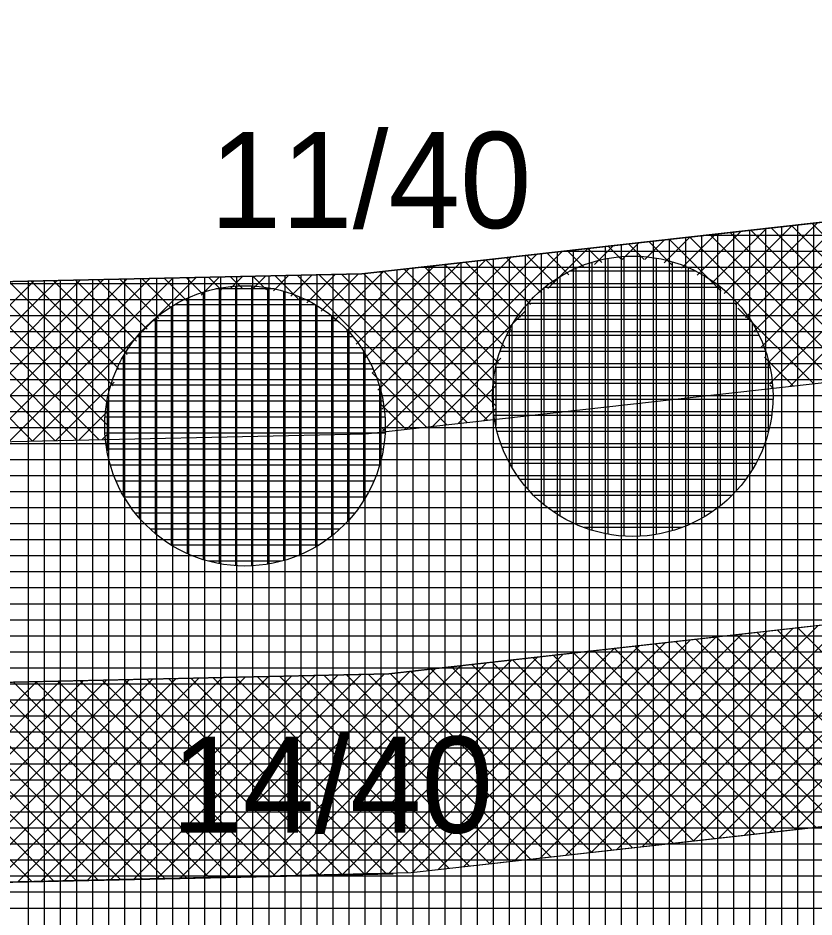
# Model space of a CAD drawing. Extents: x -566461 to -565198, y -1096301 to -1095707.
# Drawn here: x -565614.79 to -565604.86, y -1095879.32 to -1095868.1 of the extents above; entities that cross this region are included whole.
import ezdxf

# ---------------------------------------------------------------- set-up
doc = ezdxf.new("R2010")
doc.units = 0
for name, color, linetype in [('Vrstva 13', 7, 'Continuous'), ('Vrstva 40', 7, 'Continuous'), ('Vrstva 41', 7, 'Continuous'), ('Vrstva 42', 7, 'Continuous'), ('Vrstva 43', 7, 'Continuous'), ('Vrstva 44', 7, 'Continuous')]:
    doc.layers.add(name, color=color, linetype=linetype)

msp = doc.modelspace()

# ---------------------------------------------------------------- linework, layer by layer
at = {"layer": 'Vrstva 13'}
for p, q in [((-565610.5, -1095871.29), (-565587.97, -1095868.76)), ((-565630.22, -1095871.73), (-565610.5, -1095871.29)), ((-565610.165, -1095876.284), (-565587.281, -1095873.714)), ((-565609.886, -1095878.768), (-565587.002, -1095876.198)), ((-565630.41, -1095876.736), (-565610.165, -1095876.284)), ((-565630.354, -1095879.235), (-565610.109, -1095878.783))]:
    msp.add_line(p, q, dxfattribs=at)
at = {"layer": 'Vrstva 41'}
for p, q in [((-565605.453, -1095872.423), (-565603.537, -1095870.508)), ((-565605.413, -1095872.666), (-565603.219, -1095870.472)), ((-565605.161, -1095872.697), (-565602.9, -1095870.437)), ((-565605.715, -1095871.838), (-565604.493, -1095870.615)), ((-565605.608, -1095872.013), (-565604.175, -1095870.58)), ((-565605.52, -1095872.208), (-565603.856, -1095870.544)), ((-565606.14, -1095871.414), (-565605.449, -1095870.723)), ((-565605.981, -1095871.538), (-565605.131, -1095870.687)), ((-565605.839, -1095871.679), (-565604.812, -1095870.651)), ((-565603.809, -1095872.302), (-565605.395, -1095870.717)), ((-565603.807, -1095872.022), (-565605.141, -1095870.688)), ((-565603.767, -1095871.779), (-565604.886, -1095870.66)), ((-565606.727, -1095871.152), (-565606.405, -1095870.83)), ((-565606.511, -1095871.219), (-565606.086, -1095870.794)), ((-565604.608, -1095872.635), (-565606.412, -1095870.831)), ((-565606.316, -1095871.307), (-565605.768, -1095870.759)), ((-565604.353, -1095872.607), (-565606.158, -1095870.802)), ((-565604.099, -1095872.578), (-565605.903, -1095870.774)), ((-565603.844, -1095872.55), (-565605.649, -1095870.745)), ((-565607.597, -1095871.174), (-565607.361, -1095870.937)), ((-565607.262, -1095871.112), (-565607.429, -1095870.945)), ((-565607.252, -1095871.112), (-565607.042, -1095870.902)), ((-565606.979, -1095871.112), (-565607.175, -1095870.917)), ((-565606.97, -1095871.113), (-565606.724, -1095870.866)), ((-565606.632, -1095871.177), (-565606.921, -1095870.888)), ((-565606.018, -1095871.508), (-565606.666, -1095870.859)), ((-565610.253, -1095872.981), (-565608.317, -1095871.045)), ((-565610.245, -1095873.256), (-565607.998, -1095871.009)), ((-565608.095, -1095871.411), (-565608.446, -1095871.059)), ((-565607.919, -1095871.304), (-565608.192, -1095871.031)), ((-565608.181, -1095871.475), (-565607.68, -1095870.973)), ((-565607.724, -1095871.216), (-565607.938, -1095871.002)), ((-565607.507, -1095871.15), (-565607.683, -1095870.974)), ((-565610.462, -1095872.342), (-565609.273, -1095871.152)), ((-565610.371, -1095872.533), (-565608.954, -1095871.116)), ((-565610.3, -1095872.745), (-565608.635, -1095871.081)), ((-565608.629, -1095872.008), (-565609.464, -1095871.174)), ((-565608.522, -1095871.833), (-565609.209, -1095871.145)), ((-565608.397, -1095871.674), (-565608.955, -1095871.116)), ((-565608.254, -1095871.534), (-565608.701, -1095871.088)), ((-565611.009, -1095871.757), (-565610.543, -1095871.291)), ((-565610.848, -1095871.879), (-565610.229, -1095871.26)), ((-565608.932, -1095873.119), (-565610.756, -1095871.296)), ((-565610.703, -1095872.016), (-565609.91, -1095871.224)), ((-565610.573, -1095872.17), (-565609.591, -1095871.188)), ((-565608.829, -1095872.939), (-565610.481, -1095871.288)), ((-565608.827, -1095872.659), (-565610.226, -1095871.259)), ((-565608.786, -1095872.417), (-565609.972, -1095871.231)), ((-565608.718, -1095872.202), (-565609.718, -1095871.202)), ((-565613.781, -1095873.362), (-565615.736, -1095871.407)), ((-565613.681, -1095873.178), (-565615.459, -1095871.401)), ((-565615.422, -1095872.21), (-565614.593, -1095871.381)), ((-565615.303, -1095872.374), (-565614.304, -1095871.375)), ((-565615.201, -1095872.556), (-565614.014, -1095871.368)), ((-565613.658, -1095872.919), (-565615.182, -1095871.394)), ((-565615.119, -1095872.756), (-565613.725, -1095871.362)), ((-565615.062, -1095872.981), (-565613.436, -1095871.356)), ((-565615.033, -1095873.236), (-565613.146, -1095871.349)), ((-565613.605, -1095872.689), (-565614.906, -1095871.388)), ((-565614.901, -1095873.386), (-565612.857, -1095871.343)), ((-565613.529, -1095872.482), (-565614.629, -1095871.382)), ((-565614.611, -1095873.38), (-565612.568, -1095871.336)), ((-565613.431, -1095872.298), (-565614.352, -1095871.376)), ((-565613.315, -1095872.131), (-565614.076, -1095871.37)), ((-565613.182, -1095871.981), (-565613.799, -1095871.364)), ((-565613.033, -1095871.847), (-565613.522, -1095871.357)), ((-565612.868, -1095871.729), (-565613.246, -1095871.351)), ((-565612.685, -1095871.63), (-565612.969, -1095871.345)), ((-565612.481, -1095871.55), (-565612.692, -1095871.339)), ((-565612.508, -1095871.559), (-565612.279, -1095871.33)), ((-565612.253, -1095871.496), (-565612.416, -1095871.333)), ((-565612.145, -1095871.479), (-565611.989, -1095871.323)), ((-565611.996, -1095871.47), (-565612.139, -1095871.327)), ((-565611.691, -1095871.492), (-565611.862, -1095871.32)), ((-565611.857, -1095871.474), (-565611.7, -1095871.317)), ((-565611.606, -1095871.505), (-565611.411, -1095871.31)), ((-565611.297, -1095871.603), (-565611.586, -1095871.314)), ((-565611.386, -1095871.569), (-565611.121, -1095871.304)), ((-565609.441, -1095873.176), (-565611.309, -1095871.308)), ((-565611.188, -1095871.654), (-565610.832, -1095871.297)), ((-565609.186, -1095873.148), (-565611.032, -1095871.302)), ((-565614.058, -1095873.368), (-565616.012, -1095871.413)), ((-565604.862, -1095872.664), (-565605.808, -1095871.718)), ((-565609.938, -1095873.232), (-565608.465, -1095871.759)), ((-565609.62, -1095873.197), (-565608.766, -1095872.343)), ((-565605.116, -1095872.692), (-565605.477, -1095872.332)), ((-565614.334, -1095873.374), (-565615.252, -1095872.457)), ((-565609.695, -1095873.205), (-565610.373, -1095872.527)), ((-565614.322, -1095873.374), (-565613.591, -1095872.642)), ((-565609.301, -1095873.161), (-565608.828, -1095872.688)), ((-565605.371, -1095872.721), (-565605.412, -1095872.679)), ((-565614.611, -1095873.38), (-565615.075, -1095872.916)), ((-565609.949, -1095873.233), (-565610.262, -1095872.921)), ((-565608.983, -1095873.125), (-565608.827, -1095872.97)), ((-565614.033, -1095873.367), (-565613.671, -1095873.005)), ((-565613.744, -1095873.361), (-565613.676, -1095873.293)), ((-565610.204, -1095873.262), (-565610.242, -1095873.224)), ((-565605.408, -1095878.265), (-565602.575, -1095875.432)), ((-565605.09, -1095878.229), (-565602.256, -1095875.396)), ((-565606.364, -1095878.372), (-565603.531, -1095875.539)), ((-565606.046, -1095878.337), (-565603.212, -1095875.503)), ((-565605.727, -1095878.301), (-565602.893, -1095875.467)), ((-565607.32, -1095878.48), (-565604.486, -1095875.646)), ((-565607.001, -1095878.444), (-565604.168, -1095875.61)), ((-565606.683, -1095878.408), (-565603.849, -1095875.575)), ((-565608.276, -1095878.587), (-565605.442, -1095875.754)), ((-565607.957, -1095878.551), (-565605.124, -1095875.718)), ((-565607.639, -1095878.516), (-565604.805, -1095875.682)), ((-565603.309, -1095878.029), (-565605.57, -1095875.768)), ((-565603.055, -1095878.001), (-565605.316, -1095875.739)), ((-565602.801, -1095877.972), (-565605.062, -1095875.711)), ((-565609.55, -1095878.73), (-565606.717, -1095875.897)), ((-565609.232, -1095878.695), (-565606.398, -1095875.861)), ((-565608.913, -1095878.659), (-565606.08, -1095875.825)), ((-565608.595, -1095878.623), (-565605.761, -1095875.789)), ((-565604.326, -1095878.144), (-565606.588, -1095875.882)), ((-565604.072, -1095878.115), (-565606.333, -1095875.854)), ((-565603.818, -1095878.086), (-565606.079, -1095875.825)), ((-565603.563, -1095878.058), (-565605.825, -1095875.797)), ((-565610.449, -1095878.781), (-565607.673, -1095876.004)), ((-565610.16, -1095878.774), (-565607.354, -1095875.968)), ((-565609.869, -1095878.766), (-565607.035, -1095875.933)), ((-565605.343, -1095878.258), (-565607.605, -1095875.996)), ((-565605.089, -1095878.229), (-565607.35, -1095875.968)), ((-565604.835, -1095878.201), (-565607.096, -1095875.939)), ((-565604.581, -1095878.172), (-565606.842, -1095875.911)), ((-565611.318, -1095878.801), (-565608.629, -1095876.111)), ((-565611.028, -1095878.794), (-565608.31, -1095876.076)), ((-565610.739, -1095878.787), (-565607.991, -1095876.04)), ((-565606.361, -1095878.372), (-565608.622, -1095876.111)), ((-565606.106, -1095878.344), (-565608.368, -1095876.082)), ((-565605.852, -1095878.315), (-565608.113, -1095876.054)), ((-565605.598, -1095878.286), (-565607.859, -1095876.025)), ((-565612.186, -1095878.82), (-565609.584, -1095876.219)), ((-565611.897, -1095878.814), (-565609.266, -1095876.183)), ((-565611.607, -1095878.807), (-565608.947, -1095876.147)), ((-565607.378, -1095878.486), (-565609.639, -1095876.225)), ((-565607.123, -1095878.458), (-565609.385, -1095876.196)), ((-565606.869, -1095878.429), (-565609.13, -1095876.168)), ((-565606.615, -1095878.401), (-565608.876, -1095876.139)), ((-565615.37, -1095878.893), (-565612.82, -1095876.343)), ((-565615.081, -1095878.887), (-565612.531, -1095876.337)), ((-565614.791, -1095878.88), (-565612.242, -1095876.33)), ((-565614.502, -1095878.873), (-565611.952, -1095876.324)), ((-565614.212, -1095878.867), (-565611.663, -1095876.317)), ((-565613.923, -1095878.86), (-565611.374, -1095876.311)), ((-565613.633, -1095878.854), (-565611.084, -1095876.305)), ((-565613.344, -1095878.847), (-565610.795, -1095876.298)), ((-565613.055, -1095878.84), (-565610.506, -1095876.292)), ((-565610.477, -1095878.781), (-565612.913, -1095876.345)), ((-565612.765, -1095878.834), (-565610.217, -1095876.285)), ((-565610.2, -1095878.775), (-565612.636, -1095876.339)), ((-565612.476, -1095878.827), (-565609.903, -1095876.255)), ((-565609.924, -1095878.769), (-565612.359, -1095876.333)), ((-565609.666, -1095878.743), (-565612.083, -1095876.327)), ((-565609.412, -1095878.715), (-565611.806, -1095876.321)), ((-565609.158, -1095878.686), (-565611.529, -1095876.314)), ((-565608.903, -1095878.658), (-565611.253, -1095876.308)), ((-565608.649, -1095878.629), (-565610.976, -1095876.302)), ((-565608.395, -1095878.601), (-565610.699, -1095876.296)), ((-565608.141, -1095878.572), (-565610.423, -1095876.29)), ((-565607.886, -1095878.543), (-565610.148, -1095876.282)), ((-565607.632, -1095878.515), (-565609.893, -1095876.253)), ((-565617.107, -1095878.933), (-565614.556, -1095876.382)), ((-565614.625, -1095878.876), (-565617.063, -1095876.438)), ((-565616.817, -1095878.926), (-565614.267, -1095876.376)), ((-565614.348, -1095878.87), (-565616.786, -1095876.432)), ((-565616.528, -1095878.92), (-565613.977, -1095876.369)), ((-565614.072, -1095878.863), (-565616.509, -1095876.426)), ((-565616.238, -1095878.913), (-565613.688, -1095876.363)), ((-565613.795, -1095878.857), (-565616.233, -1095876.419)), ((-565613.518, -1095878.851), (-565615.956, -1095876.413)), ((-565615.949, -1095878.906), (-565613.399, -1095876.356)), ((-565613.242, -1095878.845), (-565615.679, -1095876.407)), ((-565615.66, -1095878.9), (-565613.11, -1095876.35)), ((-565612.965, -1095878.838), (-565615.403, -1095876.401)), ((-565612.689, -1095878.832), (-565615.126, -1095876.395)), ((-565612.412, -1095878.826), (-565614.849, -1095876.389)), ((-565612.136, -1095878.819), (-565614.573, -1095876.382)), ((-565611.859, -1095878.813), (-565614.296, -1095876.376)), ((-565611.583, -1095878.807), (-565614.019, -1095876.37)), ((-565611.306, -1095878.8), (-565613.743, -1095876.364)), ((-565611.03, -1095878.794), (-565613.466, -1095876.358)), ((-565610.753, -1095878.788), (-565613.189, -1095876.352))]:
    msp.add_line(p, q, dxfattribs=at)
at = {"layer": 'Vrstva 42'}
for points in [[(-565642.21, -1095870.56), (-565642.251, -1095872.566), (-565630.414, -1095873.721), (-565610.455, -1095873.29), (-565587.747, -1095870.748), (-565569.297, -1095867.734), (-565519.622, -1095865.105), (-565519.36, -1095863.08), (-565569.62, -1095865.76), (-565587.97, -1095868.76), (-565610.5, -1095871.29), (-565630.22, -1095871.73)], [(-565642.542, -1095875.552), (-565642.365, -1095878.081), (-565630.354, -1095879.235), (-565609.886, -1095878.768), (-565587.002, -1095876.198), (-565568.675, -1095873.205), (-565520.341, -1095870.651), (-565520.014, -1095868.13), (-565569.078, -1095870.738), (-565587.281, -1095873.714), (-565610.165, -1095876.284), (-565630.41, -1095876.736)]]:
    msp.add_lwpolyline(points, close=True, dxfattribs=at)
at = {"layer": 'Vrstva 43'}
for p, q in [((-565605.46, -1095885.817), (-565605.46, -1095870.724)), ((-565605.26, -1095885.794), (-565605.26, -1095870.702)), ((-565605.06, -1095885.772), (-565605.06, -1095870.679)), ((-565604.86, -1095885.75), (-565604.86, -1095870.657)), ((-565606.46, -1095885.929), (-565606.46, -1095870.836)), ((-565606.26, -1095885.907), (-565606.26, -1095870.814)), ((-565606.226, -1095870.81), (-565520.361, -1095870.81)), ((-565606.06, -1095885.884), (-565606.06, -1095870.791)), ((-565605.86, -1095885.862), (-565605.86, -1095870.769)), ((-565605.66, -1095885.839), (-565605.66, -1095870.746)), ((-565607.46, -1095886.042), (-565607.46, -1095870.949)), ((-565607.26, -1095886.019), (-565607.26, -1095870.926)), ((-565607.06, -1095885.997), (-565607.06, -1095870.904)), ((-565606.86, -1095885.974), (-565606.86, -1095870.881)), ((-565606.66, -1095885.952), (-565606.66, -1095870.859)), ((-565608.46, -1095886.154), (-565608.46, -1095871.061)), ((-565608.26, -1095886.132), (-565608.26, -1095871.038)), ((-565608.06, -1095886.109), (-565608.06, -1095871.016)), ((-565608.007, -1095871.01), (-565520.387, -1095871.01)), ((-565607.86, -1095886.087), (-565607.86, -1095870.994)), ((-565607.66, -1095886.064), (-565607.66, -1095870.971)), ((-565609.46, -1095886.267), (-565609.46, -1095871.173)), ((-565609.26, -1095886.244), (-565609.26, -1095871.151)), ((-565609.06, -1095886.222), (-565609.06, -1095871.128)), ((-565608.86, -1095886.199), (-565608.86, -1095871.106)), ((-565608.66, -1095886.177), (-565608.66, -1095871.083)), ((-565610.66, -1095886.296), (-565610.66, -1095871.294)), ((-565610.46, -1095886.292), (-565610.46, -1095871.286)), ((-565610.26, -1095886.287), (-565610.26, -1095871.263)), ((-565610.06, -1095886.283), (-565610.06, -1095871.241)), ((-565609.86, -1095886.278), (-565609.86, -1095871.218)), ((-565609.788, -1095871.21), (-565520.413, -1095871.21)), ((-565609.66, -1095886.274), (-565609.66, -1095871.196)), ((-565614.66, -1095886.387), (-565614.66, -1095871.383)), ((-565614.46, -1095886.382), (-565614.46, -1095871.378)), ((-565614.26, -1095886.378), (-565614.26, -1095871.374)), ((-565614.06, -1095886.373), (-565614.06, -1095871.369)), ((-565613.86, -1095886.369), (-565613.86, -1095871.365)), ((-565613.66, -1095886.364), (-565613.66, -1095871.361)), ((-565613.46, -1095886.36), (-565613.46, -1095871.356)), ((-565613.26, -1095886.355), (-565613.26, -1095871.352)), ((-565613.06, -1095886.35), (-565613.06, -1095871.347)), ((-565612.86, -1095886.346), (-565612.86, -1095871.343)), ((-565612.66, -1095886.341), (-565612.66, -1095871.338)), ((-565612.46, -1095886.337), (-565612.46, -1095871.334)), ((-565612.26, -1095886.332), (-565612.26, -1095871.329)), ((-565612.06, -1095886.328), (-565612.06, -1095871.325)), ((-565611.86, -1095886.323), (-565611.86, -1095871.32)), ((-565611.66, -1095886.319), (-565611.66, -1095871.316)), ((-565611.46, -1095886.314), (-565611.46, -1095871.311)), ((-565611.26, -1095886.31), (-565611.26, -1095871.307)), ((-565611.06, -1095886.305), (-565611.06, -1095871.302)), ((-565610.86, -1095886.301), (-565610.86, -1095871.298)), ((-565615.878, -1095871.41), (-565520.439, -1095871.41)), ((-565624.842, -1095871.61), (-565520.465, -1095871.61)), ((-565642.236, -1095871.81), (-565520.491, -1095871.81)), ((-565642.24, -1095872.01), (-565520.517, -1095872.01)), ((-565642.244, -1095872.21), (-565520.543, -1095872.21)), ((-565642.248, -1095872.41), (-565520.569, -1095872.41)), ((-565642.252, -1095872.61), (-565520.595, -1095872.61)), ((-565642.256, -1095872.81), (-565520.62, -1095872.81)), ((-565642.26, -1095873.01), (-565520.646, -1095873.01)), ((-565642.265, -1095873.21), (-565520.672, -1095873.21)), ((-565642.269, -1095873.41), (-565520.698, -1095873.41)), ((-565642.273, -1095873.61), (-565520.724, -1095873.61)), ((-565642.277, -1095873.81), (-565520.75, -1095873.81)), ((-565642.281, -1095874.01), (-565520.776, -1095874.01)), ((-565642.285, -1095874.21), (-565520.802, -1095874.21)), ((-565642.289, -1095874.41), (-565520.828, -1095874.41)), ((-565642.293, -1095874.61), (-565520.854, -1095874.61)), ((-565642.298, -1095874.81), (-565520.88, -1095874.81)), ((-565642.302, -1095875.01), (-565520.905, -1095875.01)), ((-565642.306, -1095875.21), (-565520.931, -1095875.21)), ((-565642.31, -1095875.41), (-565520.957, -1095875.41)), ((-565642.314, -1095875.61), (-565520.983, -1095875.61)), ((-565642.318, -1095875.81), (-565521.009, -1095875.81)), ((-565642.322, -1095876.01), (-565521.035, -1095876.01)), ((-565642.326, -1095876.21), (-565521.061, -1095876.21)), ((-565642.331, -1095876.41), (-565521.087, -1095876.41)), ((-565642.335, -1095876.61), (-565521.113, -1095876.61)), ((-565642.339, -1095876.81), (-565521.139, -1095876.81)), ((-565642.343, -1095877.01), (-565521.165, -1095877.01)), ((-565642.347, -1095877.21), (-565521.19, -1095877.21)), ((-565642.351, -1095877.41), (-565521.216, -1095877.41)), ((-565642.355, -1095877.61), (-565521.242, -1095877.61)), ((-565642.359, -1095877.81), (-565521.268, -1095877.81)), ((-565642.364, -1095878.01), (-565521.294, -1095878.01)), ((-565642.368, -1095878.21), (-565521.32, -1095878.21)), ((-565642.372, -1095878.41), (-565525.085, -1095878.41)), ((-565642.376, -1095878.61), (-565528.851, -1095878.61)), ((-565642.38, -1095878.81), (-565532.616, -1095878.81)), ((-565642.384, -1095879.01), (-565536.381, -1095879.01)), ((-565642.388, -1095879.21), (-565540.147, -1095879.21))]:
    msp.add_line(p, q, dxfattribs=at)
msp.add_lwpolyline([(-565639.56, -1095885.89), (-565630.78, -1095886.75), (-565609.49, -1095886.27), (-565595.88, -1095884.74), (-565585.92, -1095883.62), (-565568.01, -1095880.69), (-565521.32, -1095878.21), (-565519.36, -1095863.08), (-565522.03, -1095863.23), (-565569.62, -1095865.76), (-565587.97, -1095868.76), (-565610.5, -1095871.29), (-565630.22, -1095871.73), (-565642.21, -1095870.56), (-565642.52, -1095885.6), (-565645.08, -1096008.78), (-565642.11, -1096010.51)], close=True, dxfattribs=at)
at = {"layer": 'Vrstva 44'}
for p, q in [((-565607.63, -1095871.147), (-565607.63, -1095874.493)), ((-565607.43, -1095871.098), (-565607.43, -1095874.54)), ((-565607.23, -1095871.075), (-565607.23, -1095874.565)), ((-565607.03, -1095871.074), (-565607.03, -1095874.567)), ((-565606.83, -1095871.096), (-565606.83, -1095874.546)), ((-565606.63, -1095871.141), (-565606.63, -1095874.498)), ((-565606.33, -1095871.26), (-565607.912, -1095871.26)), ((-565607.83, -1095871.223), (-565607.83, -1095874.417)), ((-565606.43, -1095871.213), (-565606.43, -1095874.426)), ((-565608.03, -1095871.326), (-565608.03, -1095874.313)), ((-565606.23, -1095871.316), (-565606.23, -1095874.326)), ((-565612.48, -1095871.521), (-565612.48, -1095874.86)), ((-565611.591, -1095871.48), (-565612.324, -1095871.48)), ((-565612.28, -1095871.47), (-565612.28, -1095874.909)), ((-565612.08, -1095871.445), (-565612.08, -1095874.934)), ((-565611.88, -1095871.444), (-565611.88, -1095874.937)), ((-565611.68, -1095871.465), (-565611.68, -1095874.917)), ((-565611.48, -1095871.509), (-565611.48, -1095874.872)), ((-565608.23, -1095871.469), (-565608.23, -1095874.171)), ((-565606.019, -1095871.46), (-565608.219, -1095871.46)), ((-565606.03, -1095871.452), (-565606.03, -1095874.187)), ((-565612.68, -1095871.597), (-565612.68, -1095874.783)), ((-565611.28, -1095871.578), (-565611.28, -1095874.8)), ((-565612.88, -1095871.702), (-565612.88, -1095874.677)), ((-565611.079, -1095871.68), (-565612.841, -1095871.68)), ((-565611.08, -1095871.68), (-565611.08, -1095874.701)), ((-565605.812, -1095871.66), (-565608.43, -1095871.66)), ((-565608.43, -1095871.66), (-565608.43, -1095873.979)), ((-565605.83, -1095871.64), (-565605.83, -1095874.002)), ((-565613.08, -1095871.848), (-565613.08, -1095874.533)), ((-565610.88, -1095871.815), (-565610.88, -1095874.565)), ((-565610.803, -1095871.88), (-565613.118, -1095871.88)), ((-565608.63, -1095871.936), (-565608.63, -1095873.703)), ((-565605.658, -1095871.86), (-565608.581, -1095871.86)), ((-565605.63, -1095871.906), (-565605.63, -1095873.737)), ((-565610.608, -1095872.08), (-565613.31, -1095872.08)), ((-565613.28, -1095872.042), (-565613.28, -1095874.338)), ((-565610.68, -1095872), (-565610.68, -1095874.382)), ((-565605.546, -1095872.06), (-565608.695, -1095872.06)), ((-565610.468, -1095872.28), (-565613.454, -1095872.28)), ((-565610.48, -1095872.26), (-565610.48, -1095874.122)), ((-565605.463, -1095872.26), (-565608.777, -1095872.26)), ((-565613.48, -1095872.325), (-565613.48, -1095874.057)), ((-565605.43, -1095872.373), (-565605.43, -1095873.274)), ((-565610.361, -1095872.48), (-565613.558, -1095872.48)), ((-565605.408, -1095872.46), (-565608.831, -1095872.46)), ((-565608.83, -1095872.457), (-565608.83, -1095873.185)), ((-565610.287, -1095872.68), (-565613.632, -1095872.68)), ((-565610.28, -1095872.707), (-565610.28, -1095873.675)), ((-565605.379, -1095872.66), (-565608.861, -1095872.66)), ((-565605.372, -1095872.86), (-565608.868, -1095872.86)), ((-565610.24, -1095872.88), (-565613.681, -1095872.88)), ((-565613.68, -1095872.877), (-565613.68, -1095873.502)), ((-565610.215, -1095873.08), (-565613.706, -1095873.08)), ((-565605.388, -1095873.06), (-565608.853, -1095873.06)), ((-565610.214, -1095873.28), (-565613.707, -1095873.28)), ((-565605.427, -1095873.26), (-565608.812, -1095873.26)), ((-565610.234, -1095873.48), (-565613.684, -1095873.48)), ((-565605.493, -1095873.46), (-565608.747, -1095873.46)), ((-565610.282, -1095873.68), (-565613.638, -1095873.68)), ((-565605.587, -1095873.66), (-565608.654, -1095873.66)), ((-565605.713, -1095873.86), (-565608.526, -1095873.86)), ((-565610.354, -1095873.88), (-565613.567, -1095873.88)), ((-565610.454, -1095874.08), (-565613.466, -1095874.08)), ((-565605.888, -1095874.06), (-565608.353, -1095874.06)), ((-565610.593, -1095874.28), (-565613.327, -1095874.28)), ((-565606.129, -1095874.26), (-565608.111, -1095874.26)), ((-565610.778, -1095874.48), (-565613.14, -1095874.48)), ((-565606.51, -1095874.46), (-565607.726, -1095874.46)), ((-565611.043, -1095874.68), (-565612.875, -1095874.68)), ((-565611.507, -1095874.88), (-565612.411, -1095874.88))]:
    msp.add_line(p, q, dxfattribs=at)
for centre in [(-565607.12, -1095872.82), (-565611.96, -1095873.19)]:
    msp.add_circle(centre, 1.75, dxfattribs=at)

# ---------------------------------------------------------------- texts
at = {"layer": 'Vrstva 40'}
for s, p in [('11/40', (-565612.4, -1095870.72)), ('14/40', (-565612.88, -1095878.27))]:
    msp.add_text(s, height=1.2, dxfattribs=at).set_placement(p)

doc.saveas('drawing.dxf')
